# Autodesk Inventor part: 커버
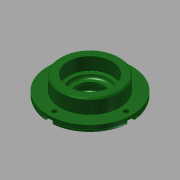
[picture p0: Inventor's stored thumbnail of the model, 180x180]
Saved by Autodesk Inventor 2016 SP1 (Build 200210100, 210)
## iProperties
Company: 한국ATC센터
Created: 2016-04
Part Number: 커버
Document SubType Name: Modeling
Designer: mdu
Density: 7.86 g/cm^3
Mass: 322.747 g
Surface Area: 149.142 cm^2
Volume: 41.0619 cm^3
Material: 강철, 연강
Appearance: 진녹색
Author: mdu
Revision Number: 1
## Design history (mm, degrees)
sketch "스케치1"
  geometry: C1 r 38 at (0, 0); 1 further point
  constraints: 1 centre point, 1 coincident
  dimensions: "d0" = 76 diameter of C1
extrude "돌출1" new body sketch "스케치1" distance "d1" = 7; taper "d2" = 0 deg
sketch "스케치2"
  geometry: C1 r 27 at (0, 0); 1 further point
  constraints: 1 centre point, 1 coincident
  dimensions: "d3" = 54 diameter of C1
extrude "돌출2" join sketch "스케치2" distance "d4" = 13; taper "d5" = 0 deg
sketch "스케치3"
  geometry: C1 r 20 at (0, 0); 1 further point
  constraints: 1 centre point, 1 coincident
  dimensions: "d6" = 40 diameter of C1
extrude "돌출3" join sketch "스케치3" distance "d7" = 5; taper "d8" = 0 deg
hole "구멍1" diameter "d11" = 25; stored, may be unused: countersink angle "d15" = 90 deg, drill point angle "d17" = 118 deg; dims "d9" = 10, "d10" = 10, "d12" = 6, "d13" = 32, "d14" = 8.3, "d16" = 8
hole "구멍2" diameter "d20" = 34; stored, may be unused: countersink angle "d24" = 90 deg, drill point angle "d26" = 0 deg; dims "d18" = 10, "d19" = 10, "d21" = 6, "d22" = 40, "d23" = 12, "d25" = 3
fillet "모깎기2" dims "d34" = 3
fillet "모깎기1" dims "d27" = 0.3
chamfer "모따기1" distance "d28" = 1; stored, may be unused: second distance "d29" = 2, angle "d30" = 45 deg
chamfer "모따기2" distance "d31" = 1.2; stored, may be unused: second distance "d32" = 2, angle "d33" = 30 deg
sketch "스케치4" dims "d35" = 65
  geometry: 3 further points
  constraints: 2 horizontal alignment, 1 coincident, 2 other
hole "구멍3" sketch "스케치4" at (32.5, 0) diameter "d36" = 4.5; stored, may be unused: countersink angle "d40" = 90 deg, drill point angle "d42" = 118 deg; dims "d37" = 6, "d38" = 8, "d39" = 4.4, "d41" = 13
sketch "스케치5"
  geometry: L1 (0, 4)-(5.5, 4); L2 (5.5, 4)-(5.5, -4); L3 (5.5, -4)-(0, -4); L4 (0, -4)-(0, 4); C1 r 2.25 at (0, 0) reference; C2 r 38 at (-32.5, 0) reference; 2 further points
  constraints: 8 end point, 3 horizontal, 2 parallel, 1 perpendicular, 1 tangent, 1 vertical alignment, 1 other
extrude "돌출4" cut sketch "스케치5" stored distance "d47" = 24.5; taper "d48" = 0 deg
node "솔리드1"
pattern_circular "원형 패턴1" dims angle "d44" = 360 deg
pattern_circular "원형 패턴2" dims angle "d50" = 360 deg
node "투영된 루프1"
